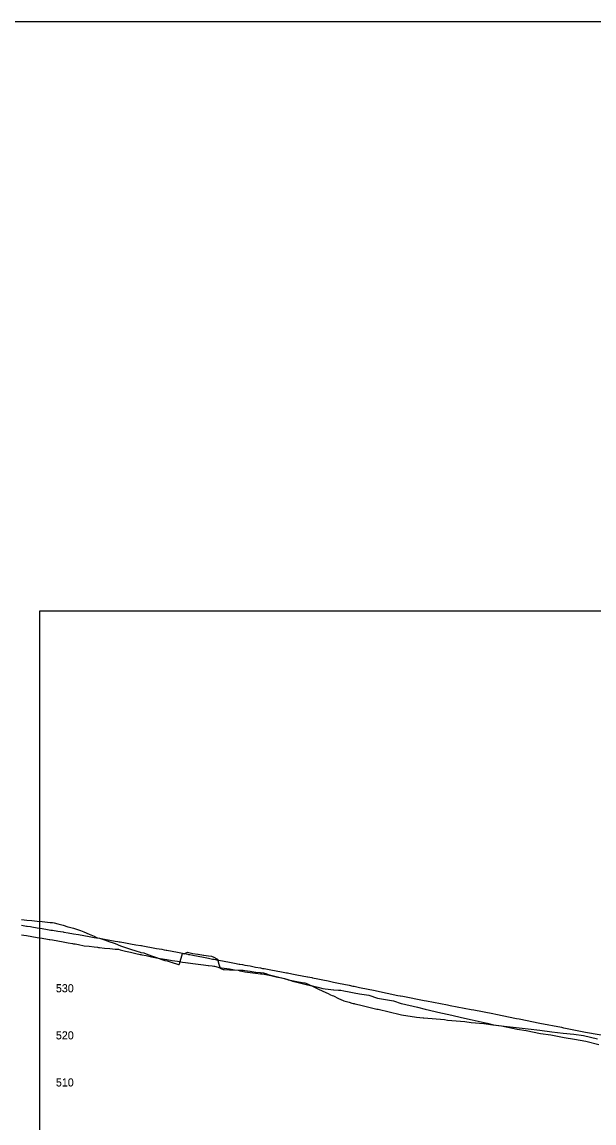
# Model space of a CAD drawing. Extents: x 2167726 to 2171326, y 1079832 to 1082032.
# Drawn here: x 2168394 to 2169001, y 1080863 to 1082032 of the extents above; entities that cross this region are included whole.
import ezdxf

# ---------------------------------------------------------------- set-up
doc = ezdxf.new("R2010")
doc.units = 0
for name, color, linetype in [('BR_EXIST_GROUND_LT', 7, 'Continuous'), ('BR_EXIST_GROUND_RT', 7, 'Continuous'), ('RD_DDB_ElevTX', 7, 'Continuous'), ('RD_DDB_Profile_EX', 7, 'Continuous'), ('RD_SHT_IplotShp', 7, 'Continuous'), ('RD_SHT_ShtClip', 7, 'Continuous')]:
    doc.layers.add(name, color=color, linetype=linetype)

msp = doc.modelspace()

# ---------------------------------------------------------------- linework, layer by layer
at = {"layer": 'BR_EXIST_GROUND_LT'}
msp.add_lwpolyline([(2168393.2, 1081078.9), (2168398.9, 1081078.2), (2168404.3, 1081077.7), (2168409.8, 1081077.1), (2168415.3, 1081076.6), (2168420.8, 1081076.1), (2168423.6, 1081075.8), (2168426.3, 1081075.6), (2168428.1, 1081075.4), (2168431.9, 1081074.3), (2168437.4, 1081072.7), (2168442.6, 1081071.2), (2168442.9, 1081071.1), (2168448.4, 1081069.7), (2168453.9, 1081067.9), (2168455.9, 1081067.2), (2168459.4, 1081065.7), (2168465, 1081063.3), (2168470.5, 1081061), (2168473, 1081059.8), (2168476, 1081058.9), (2168481.5, 1081057.1), (2168487, 1081055.3), (2168490.5, 1081054.2), (2168492.6, 1081053.3), (2168498.3, 1081051), (2168503.6, 1081049.2), (2168509.1, 1081047.4), (2168514.6, 1081045.5), (2168519.2, 1081044), (2168520.1, 1081043.8), (2168523.1, 1081043.3), (2168525.7, 1081042.4), (2168531.2, 1081040.4), (2168536.7, 1081038.4), (2168542.2, 1081036.4), (2168545.4, 1081035.3), (2168547.9, 1081034.8), (2168553.3, 1081033.2), (2168558.8, 1081031.6), (2168560, 1081031.2), (2168560.6, 1081031.2), (2168561, 1081031.8), (2168564.1, 1081042.7), (2168565.9, 1081042.5), (2168569.6, 1081044), (2168575.3, 1081042.9), (2168580.4, 1081042), (2168580.8, 1081041.9), (2168586.4, 1081041), (2168586.8, 1081040.9), (2168591.9, 1081040.4), (2168595.1, 1081040), (2168597.4, 1081038.8), (2168600.6, 1081037.1), (2168601.2, 1081036.8), (2168602.9, 1081031.4), (2168604.2, 1081027.3), (2168605.6, 1081026.5), (2168607.3, 1081025.8), (2168608.4, 1081025.8), (2168613.9, 1081025.5), (2168619.5, 1081025.3), (2168625, 1081025.1), (2168628.4, 1081025), (2168630.5, 1081024.7), (2168636, 1081023.9), (2168641.5, 1081023.1), (2168642.1, 1081023), (2168647.1, 1081022.6), (2168650.2, 1081022.4), (2168652.6, 1081021.5), (2168656, 1081020.2), (2168658.1, 1081019.6), (2168663.6, 1081018.3), (2168669.1, 1081016.9), (2168674.6, 1081015.6), (2168675, 1081015.5), (2168680.2, 1081013.6), (2168681.1, 1081013.2), (2168685.7, 1081012.2), (2168691.2, 1081010.9), (2168696.7, 1081009.6), (2168699.9, 1081008.9), (2168702.2, 1081008.3), (2168707.8, 1081006.9), (2168713.3, 1081005.6), (2168715.5, 1081005.1), (2168718.8, 1081004.8), (2168724.3, 1081004.3), (2168724.8, 1081004.3), (2168729.8, 1081003.9), (2168732.3, 1081003.7), (2168735.3, 1081003.1), (2168740.9, 1081002.1), (2168746.4, 1081001.1), (2168751.9, 1081000.1), (2168761.9, 1080998.4), (2168771.1, 1080995.2), (2168788.2, 1080992.5), (2168796.2, 1080989.7), (2168796.7, 1080989.5), (2168813.5, 1080985.6), (2168821.7, 1080983.7), (2168838.5, 1080979.9), (2168846.7, 1080978), (2168863.6, 1080974.1), (2168871.6, 1080972.3), (2168887.5, 1080968.7), (2168894.3, 1080967.1), (2168902.9, 1080965.8), (2168919.3, 1080962.4), (2168929, 1080961), (2168944.3, 1080957.8), (2168955.2, 1080956.3), (2168969.2, 1080953.4), (2168980.3, 1080951.9), (2168992.2, 1080949.5), (2169006, 1080946.2)], dxfattribs=at)
at = {"layer": 'BR_EXIST_GROUND_RT'}
msp.add_lwpolyline([(2168393.2, 1081062.6), (2168395.9, 1081062.1), (2168398.7, 1081061.9), (2168404.2, 1081060.7), (2168409.8, 1081059.8), (2168415.3, 1081058.9), (2168420.8, 1081058), (2168422.6, 1081057.7), (2168423.5, 1081057.6), (2168426.3, 1081057.1), (2168431.9, 1081056.1), (2168437.4, 1081055.2), (2168442.9, 1081054.2), (2168447.4, 1081053.4), (2168448.6, 1081053.2), (2168449, 1081053.2), (2168450.1, 1081053), (2168453.9, 1081052.2), (2168459.7, 1081051), (2168465, 1081050.4), (2168470.5, 1081049.8), (2168474, 1081049.4), (2168474.9, 1081049.2), (2168476, 1081049.1), (2168481.5, 1081048.5), (2168487, 1081048), (2168492.6, 1081047.5), (2168496.1, 1081047.2), (2168498.1, 1081046.7), (2168503.6, 1081045.3), (2168509.1, 1081044), (2168514.6, 1081042.8), (2168519.1, 1081041.8), (2168520.1, 1081041.6), (2168521.2, 1081041.5), (2168525.7, 1081040.5), (2168531.2, 1081039.3), (2168536.7, 1081038.2), (2168542.2, 1081037.1), (2168543, 1081037), (2168545.2, 1081036.7), (2168547.7, 1081036.3), (2168553.3, 1081035.4), (2168558.8, 1081034.5), (2168564.3, 1081033.7), (2168567.2, 1081033.3), (2168569.8, 1081032.9), (2168570.3, 1081032.8), (2168575.3, 1081032.1), (2168580.8, 1081031.4), (2168586.4, 1081030.7), (2168591.5, 1081030.1), (2168591.9, 1081030), (2168595.5, 1081029.6), (2168597.4, 1081029.4), (2168598, 1081029.3), (2168602, 1081028.2), (2168602.9, 1081028), (2168608.4, 1081027.1), (2168613.9, 1081026.3), (2168619.5, 1081025.4), (2168623.1, 1081024.9), (2168625, 1081024.4), (2168627, 1081023.9), (2168630.5, 1081023.4), (2168636, 1081022.7), (2168641.5, 1081022), (2168647.1, 1081021.3), (2168648.3, 1081021.2), (2168650.7, 1081020.9), (2168651.3, 1081020.7), (2168652.6, 1081020.4), (2168658.1, 1081019.3), (2168663.6, 1081018.1), (2168669.1, 1081017), (2168672.5, 1081016.3), (2168674.6, 1081015.5), (2168676.4, 1081014.8), (2168680.2, 1081014.1), (2168685.7, 1081013), (2168691.2, 1081012), (2168694.1, 1081011.5), (2168696.7, 1081010.5), (2168698.3, 1081009.9), (2168702.2, 1081008), (2168707.8, 1081005.3), (2168713.3, 1081002.7), (2168718.8, 1081000.2), (2168721.3, 1080999), (2168723.1, 1080998.3), (2168724.3, 1080997.7), (2168729.8, 1080995.1), (2168734.6, 1080992.9), (2168735.3, 1080992.6), (2168740.9, 1080991), (2168743.9, 1080990.1), (2168745.4, 1080989.7), (2168746.4, 1080989.5), (2168747.1, 1080989.3), (2168751.9, 1080988.2), (2168770.5, 1080983.8), (2168771.9, 1080983.5), (2168795.3, 1080978), (2168796.6, 1080977.7), (2168812.4, 1080975.2), (2168819.6, 1080974.5), (2168820.3, 1080974.5), (2168842.2, 1080972.5), (2168845.4, 1080972.1), (2168864, 1080970.4), (2168870.5, 1080969.6), (2168883.9, 1080968.3), (2168893.4, 1080967.1), (2168905.6, 1080965.7), (2168918.4, 1080964.1), (2168931.1, 1080962.7), (2168943.3, 1080961.2), (2168956.3, 1080959.7), (2168968.3, 1080958.2), (2168979.5, 1080957), (2168989.8, 1080955.7), (2169004.8, 1080952.3)], dxfattribs=at)
at = {"layer": 'RD_DDB_Profile_EX'}
msp.add_lwpolyline([(2168393.2, 1081072.8), (2168398.7, 1081071.9), (2168399.4, 1081071.8), (2168402.7, 1081071.3), (2168404.3, 1081071), (2168409.8, 1081070.1), (2168415.3, 1081069.2), (2168420.8, 1081068.3), (2168424.4, 1081067.7), (2168426.3, 1081067.4), (2168431.9, 1081066.5), (2168437.4, 1081065.6), (2168438.4, 1081065.4), (2168442.9, 1081064.7), (2168448.6, 1081063.7), (2168453.9, 1081062.8), (2168459.4, 1081061.9), (2168465, 1081060.9), (2168470.5, 1081059.9), (2168473, 1081059.5), (2168473.6, 1081059.3), (2168476, 1081058.9), (2168481.5, 1081058), (2168487, 1081057), (2168492.6, 1081056), (2168495.7, 1081055.4), (2168497, 1081055.2), (2168498.1, 1081055), (2168503.6, 1081054), (2168509.1, 1081053.1), (2168514.6, 1081052.1), (2168520.1, 1081051.1), (2168520.5, 1081051.1), (2168522, 1081050.8), (2168525.7, 1081050.2), (2168531.2, 1081049.2), (2168536.7, 1081048.2), (2168542.2, 1081047.2), (2168544.9, 1081046.8), (2168546.8, 1081046.4), (2168547.7, 1081046.2), (2168553.3, 1081045.2), (2168558.8, 1081044.1), (2168564.3, 1081043), (2168569.8, 1081042), (2168570.5, 1081041.8), (2168571.8, 1081041.6), (2168575.3, 1081040.9), (2168580.8, 1081039.8), (2168586.4, 1081038.8), (2168591.9, 1081037.7), (2168595.9, 1081036.9), (2168596.8, 1081036.7), (2168597.4, 1081036.6), (2168599.2, 1081036.3), (2168600.1, 1081036.1), (2168602.9, 1081035.6), (2168608.4, 1081034.6), (2168613.9, 1081033.5), (2168619.5, 1081032.5), (2168624.3, 1081031.6), (2168625, 1081031.5), (2168628, 1081030.9), (2168630.5, 1081030.5), (2168636, 1081029.5), (2168641.5, 1081028.4), (2168647.1, 1081027.4), (2168649.2, 1081027), (2168650.9, 1081026.7), (2168652.6, 1081026.4), (2168658.1, 1081025.4), (2168663.6, 1081024.3), (2168669.1, 1081023.3), (2168674.6, 1081022.3), (2168675.6, 1081022.1), (2168680.2, 1081021.2), (2168685.7, 1081020.2), (2168691.2, 1081019.1), (2168696.7, 1081018.1), (2168697.1, 1081018), (2168699.2, 1081017.6), (2168701.3, 1081017.1), (2168702.2, 1081016.9), (2168707.8, 1081015.8), (2168713.3, 1081014.7), (2168718.8, 1081013.6), (2168724.3, 1081012.4), (2168729.8, 1081011.3), (2168735.3, 1081010.2), (2168740.9, 1081009), (2168744.9, 1081008.2), (2168745.2, 1081008.1), (2168746.4, 1081007.9), (2168751.9, 1081006.7), (2168768.8, 1081003.3), (2168770.2, 1081003), (2168792.8, 1080998.3), (2168795.1, 1080997.9), (2168795.6, 1080997.8), (2168798.1, 1080997.3), (2168820.6, 1080993), (2168823.3, 1080992.4), (2168845.6, 1080988.2), (2168848.4, 1080987.6), (2168870.5, 1080983.4), (2168873.4, 1080982.8), (2168893.7, 1080978.9), (2168896.8, 1080978.3), (2168918.6, 1080973.9), (2168921.5, 1080973.4), (2168943.6, 1080968.9), (2168966.3, 1080964.4), (2168968.6, 1080963.9), (2168970.7, 1080963.5), (2168991.8, 1080959.3), (2168993.9, 1080958.9), (2169016.8, 1080954.9)], dxfattribs=at)
at = {"layer": 'RD_SHT_IplotShp'}
msp.add_lwpolyline([(2167726.1, 1079832), (2171326.1, 1079832), (2171326.1, 1082032), (2167726.1, 1082032)], close=True, dxfattribs=at)
at = {"layer": 'RD_SHT_ShtClip'}
msp.add_lwpolyline([(2168412.7, 1081406.6), (2170212.7, 1081406.6), (2170212.7, 1080306.6), (2168412.7, 1080306.6)], close=True, dxfattribs=at)

# ---------------------------------------------------------------- texts
at = {"layer": 'RD_DDB_ElevTX'}
for s, p in [('530', (2168429.8, 1081001.7)), ('530', (2168429.8, 1081001.5)), ('520', (2168429.8, 1080951.7)), ('520', (2168429.8, 1080951.5)), ('510', (2168429.8, 1080901.7)), ('510', (2168429.8, 1080901.5))]:
    msp.add_text(s, height=8.5, dxfattribs=at).set_placement(p)

doc.saveas('drawing.dxf')
